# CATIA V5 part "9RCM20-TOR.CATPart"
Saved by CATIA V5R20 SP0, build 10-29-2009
Part number: 9RCM20-TOR
Revision: ANY
Definition: UNKNOWN
Nomenclature: 9RCM20-TOR
Source: Unknown
Bounding box of the stored display mesh (mm): x -8 to 8, y -8 to 8, z -16.4 to 4.2
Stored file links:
  C:\Users\Utente\Desktop\IO LAVORO\3D X SITO CF\CUMSA\3D files RCM\RCM 204810\9RCM20-TOR.CATPart
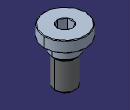
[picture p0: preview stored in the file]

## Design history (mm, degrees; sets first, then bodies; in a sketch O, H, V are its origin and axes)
Body1 "Cortar-Extruir3" (main body)
  Solid1: solid without history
